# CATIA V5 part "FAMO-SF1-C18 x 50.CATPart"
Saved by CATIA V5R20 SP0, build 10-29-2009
Part number: FAMO-SF1-C18 x 50
Definition: NONE
Nomenclature: FAMO-SF1-C18 x 50
Source: Unknown
Description: FAMO-SF1-C18 x 50
Bounding box of the stored display mesh (mm): x -32 to 18, y -17 to 17, z -17 to 17
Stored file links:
  C:\Users\Utente\Desktop\IO LAVORO\3D X SITO CF\X SITO\FAMO\FAMO-SF1-C18 x 50.CATPart

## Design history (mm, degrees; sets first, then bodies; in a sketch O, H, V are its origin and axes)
Body1 "FAMO-SF1-C18 x 50" (main body)
  Solid1: solid without history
